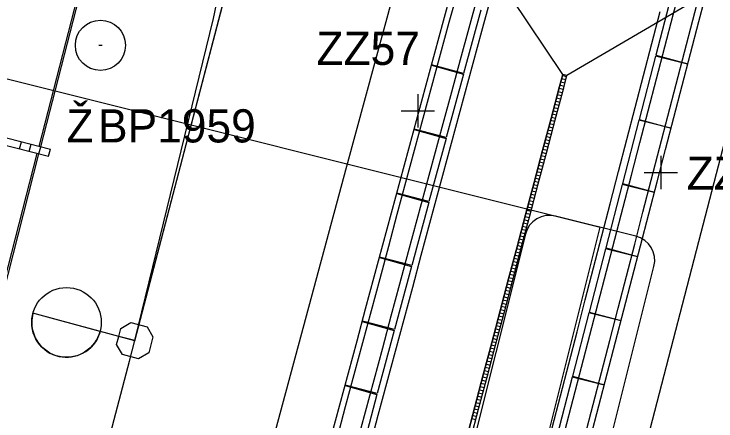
# Model space of a CAD drawing. Extents: x -733601 to -733291, y -1137892 to -1137187.
# Drawn here: x -733436.26 to -733415.08, y -1137594.6 to -1137582.33 of the extents above; entities that cross this region are included whole.
import ezdxf

# ---------------------------------------------------------------- set-up
doc = ezdxf.new("R2010")
doc.units = 0
for name, color, linetype in [('BP_ZBP_a_ZZ', 7, 'Continuous'), ('Default', 7, 'Continuous'), ('SIT_PROJ', 7, 'Continuous'), ('SIT_PUV_ZELEZNICE', 7, 'Continuous')]:
    doc.layers.add(name, color=color, linetype=linetype)

# ---------------------------------------------------------------- blocks, each defined once
blk = doc.blocks.new('T_PS_1_4')
at = {"layer": 'Default'}
blk.add_line((-12.486, 3.717), (12.486, 3.717), dxfattribs=at)
for points in [[(10.986, 8), (-10.986, 8)], [(-12.486, 6.5), (-12.486, 1.5)], [(12.486, 1.5), (12.486, 6.5)], [(-10.986, 0), (10.986, 0)]]:
    blk.add_lwpolyline(points, dxfattribs=at)
for centre, start, end in [((-10.986, 6.5), 90, 180), ((10.986, 6.5), 0, 90), ((-10.986, 1.5), 180, 270), ((10.986, 1.5), 270, 360)]:
    blk.add_arc(centre, 1.5, start, end, dxfattribs=at)
blk.add_text('SO', height=2.7, dxfattribs=at).set_placement((-11.75, 4.466))

msp = doc.modelspace()

# ---------------------------------------------------------------- linework, layer by layer
at = {"layer": 'BP_ZBP_a_ZZ'}
for p, q in [((-733433.7, -1137583.274), (-733433.6, -1137583.274)), ((-733424.074, -1137584.748), (-733424.074, -1137585.748)), ((-733424.574, -1137585.248), (-733423.574, -1137585.248)), ((-733416.743, -1137586.608), (-733416.743, -1137587.608)), ((-733417.243, -1137587.108), (-733416.243, -1137587.108))]:
    msp.add_line(p, q, dxfattribs=at)
msp.add_circle((-733433.65, -1137583.274), 0.756, dxfattribs=at)
at = {"layer": 'SIT_PROJ'}
msp.add_lwpolyline([(-733437.916, -1137583.919), (-733418.568, -1137588.759), (-733418.568, -1137588.759)], dxfattribs=at)
at = {"layer": 'SIT_PUV_ZELEZNICE'}
for p, q in [((-733435.499, -1137586.32), (-733431.375, -1137570.31)), ((-733435.451, -1137586.332), (-733431.338, -1137570.368)), ((-733419.7, -1137584.149), (-733422.437, -1137580.057)), ((-733416.398, -1137581.663), (-733416.895, -1137583.569)), ((-733415.601, -1137581.855), (-733419.575, -1137584.182)), ((-733422.176, -1137582.218), (-733422.692, -1137584.119)), ((-733416.895, -1137583.569), (-733415.93, -1137583.831)), ((-733416.903, -1137583.599), (-733417.399, -1137585.505)), ((-733415.933, -1137583.841), (-733416.903, -1137583.599)), ((-733423.662, -1137583.876), (-733422.7, -1137584.148)), ((-733422.692, -1137584.119), (-733423.66, -1137583.867)), ((-733422.7, -1137584.148), (-733423.215, -1137586.049)), ((-733419.585, -1137584.222), (-733419.711, -1137584.188)), ((-733419.575, -1137584.182), (-733419.7, -1137584.149)), ((-733419.637, -1137584.415), (-733419.762, -1137584.382)), ((-733419.611, -1137584.318), (-733419.737, -1137584.285)), ((-733419.688, -1137584.608), (-733419.814, -1137584.575)), ((-733419.662, -1137584.512), (-733419.788, -1137584.478)), ((-733419.765, -1137584.898), (-733419.891, -1137584.865)), ((-733419.739, -1137584.801), (-733419.865, -1137584.768)), ((-733419.714, -1137584.705), (-733419.839, -1137584.672)), ((-733419.816, -1137585.091), (-733419.942, -1137585.058)), ((-733419.79, -1137584.995), (-733419.916, -1137584.962)), ((-733419.867, -1137585.285), (-733419.993, -1137585.252)), ((-733419.842, -1137585.188), (-733419.967, -1137585.155)), ((-733419.919, -1137585.478), (-733420.044, -1137585.445)), ((-733419.893, -1137585.381), (-733420.019, -1137585.348)), ((-733419.97, -1137585.671), (-733420.096, -1137585.638)), ((-733419.944, -1137585.575), (-733420.07, -1137585.541)), ((-733417.407, -1137585.534), (-733417.903, -1137587.441)), ((-733416.437, -1137585.776), (-733417.407, -1137585.534)), ((-733417.399, -1137585.505), (-733416.434, -1137585.767)), ((-733437.194, -1137585.883), (-733435.16, -1137586.407)), ((-733424.186, -1137585.807), (-733423.223, -1137586.078)), ((-733423.215, -1137586.049), (-733424.183, -1137585.797)), ((-733420.021, -1137585.865), (-733420.147, -1137585.831)), ((-733419.996, -1137585.768), (-733420.121, -1137585.735)), ((-733437.249, -1137586.096), (-733435.215, -1137586.62)), ((-733423.223, -1137586.078), (-733423.738, -1137587.979)), ((-733420.098, -1137586.155), (-733420.224, -1137586.121)), ((-733420.073, -1137586.058), (-733420.198, -1137586.025)), ((-733420.047, -1137585.961), (-733420.173, -1137585.928)), ((-733436.087, -1137586.396), (-733436.032, -1137586.183)), ((-733435.796, -1137586.471), (-733435.741, -1137586.258)), ((-733435.506, -1137586.546), (-733435.451, -1137586.332)), ((-733420.15, -1137586.348), (-733420.275, -1137586.315)), ((-733420.124, -1137586.251), (-733420.25, -1137586.218)), ((-733438.815, -1137599.192), (-733435.554, -1137586.533)), ((-733438.766, -1137599.204), (-733435.506, -1137586.546)), ((-733435.215, -1137586.62), (-733435.16, -1137586.407)), ((-733420.201, -1137586.541), (-733420.327, -1137586.508)), ((-733420.175, -1137586.445), (-733420.301, -1137586.411)), ((-733420.252, -1137586.735), (-733420.378, -1137586.701)), ((-733420.226, -1137586.638), (-733420.352, -1137586.605)), ((-733420.303, -1137586.928), (-733420.429, -1137586.895)), ((-733420.278, -1137586.831), (-733420.403, -1137586.798)), ((-733420.38, -1137587.218), (-733420.506, -1137587.185)), ((-733420.355, -1137587.121), (-733420.48, -1137587.088)), ((-733420.329, -1137587.025), (-733420.455, -1137586.991)), ((-733420.431, -1137587.411), (-733420.557, -1137587.378)), ((-733420.406, -1137587.315), (-733420.532, -1137587.281)), ((-733420.483, -1137587.605), (-733420.608, -1137587.571)), ((-733420.457, -1137587.508), (-733420.583, -1137587.475)), ((-733417.91, -1137587.47), (-733418.406, -1137589.377)), ((-733416.94, -1137587.712), (-733417.91, -1137587.47)), ((-733417.903, -1137587.441), (-733416.938, -1137587.702)), ((-733424.708, -1137587.737), (-733423.745, -1137588.008)), ((-733423.738, -1137587.979), (-733424.705, -1137587.728)), ((-733420.534, -1137587.798), (-733420.66, -1137587.765)), ((-733420.508, -1137587.701), (-733420.634, -1137587.668)), ((-733423.745, -1137588.008), (-733424.259, -1137589.91)), ((-733420.585, -1137587.991), (-733420.711, -1137587.958)), ((-733420.559, -1137587.895), (-733420.685, -1137587.861)), ((-733420.662, -1137588.281), (-733420.788, -1137588.248)), ((-733420.636, -1137588.185), (-733420.762, -1137588.151)), ((-733420.611, -1137588.088), (-733420.736, -1137588.055)), ((-733420.713, -1137588.475), (-733420.839, -1137588.441)), ((-733420.688, -1137588.378), (-733420.813, -1137588.345)), ((-733420.764, -1137588.668), (-733420.89, -1137588.635)), ((-733420.739, -1137588.571), (-733420.864, -1137588.538)), ((-733420.816, -1137588.861), (-733420.941, -1137588.828)), ((-733420.79, -1137588.765), (-733420.916, -1137588.731)), ((-733420.867, -1137589.055), (-733420.992, -1137589.021)), ((-733420.841, -1137588.958), (-733420.967, -1137588.925)), ((-733420.943, -1137589.345), (-733421.069, -1137589.311)), ((-733420.918, -1137589.248), (-733421.044, -1137589.215)), ((-733420.892, -1137589.151), (-733421.018, -1137589.118)), ((-733420.995, -1137589.538), (-733421.12, -1137589.505)), ((-733420.969, -1137589.441), (-733421.095, -1137589.408)), ((-733418.414, -1137589.406), (-733418.909, -1137591.313)), ((-733417.443, -1137589.648), (-733418.414, -1137589.406)), ((-733418.406, -1137589.377), (-733417.441, -1137589.638)), ((-733425.229, -1137589.668), (-733424.267, -1137589.938)), ((-733424.259, -1137589.91), (-733425.227, -1137589.659)), ((-733421.046, -1137589.731), (-733421.171, -1137589.698)), ((-733421.02, -1137589.635), (-733421.146, -1137589.601)), ((-733424.267, -1137589.938), (-733424.779, -1137591.84)), ((-733421.097, -1137589.925), (-733421.223, -1137589.891)), ((-733421.071, -1137589.828), (-733421.197, -1137589.795)), ((-733421.148, -1137590.118), (-733421.274, -1137590.085)), ((-733421.123, -1137590.021), (-733421.248, -1137589.988)), ((-733421.199, -1137590.311), (-733421.325, -1137590.278)), ((-733421.174, -1137590.215), (-733421.299, -1137590.181)), ((-733421.276, -1137590.601), (-733421.402, -1137590.568)), ((-733421.25, -1137590.505), (-733421.376, -1137590.471)), ((-733421.225, -1137590.408), (-733421.35, -1137590.375)), ((-733421.327, -1137590.795), (-733421.453, -1137590.761)), ((-733421.301, -1137590.698), (-733421.427, -1137590.665)), ((-733421.378, -1137590.988), (-733421.504, -1137590.955)), ((-733421.353, -1137590.891), (-733421.478, -1137590.858)), ((-733421.429, -1137591.181), (-733421.555, -1137591.148)), ((-733421.404, -1137591.085), (-733421.529, -1137591.052)), ((-733432.613, -1137592.178), (-733435.685, -1137591.349)), ((-733421.48, -1137591.375), (-733421.606, -1137591.342)), ((-733421.455, -1137591.278), (-733421.581, -1137591.245)), ((-733418.917, -1137591.342), (-733419.411, -1137593.249)), ((-733417.946, -1137591.583), (-733418.917, -1137591.342)), ((-733418.909, -1137591.313), (-733417.944, -1137591.574)), ((-733433.033, -1137591.809), (-733432.728, -1137591.63)), ((-733432.728, -1137591.63), (-733432.244, -1137591.757)), ((-733425.75, -1137591.599), (-733424.787, -1137591.869)), ((-733424.779, -1137591.84), (-733425.747, -1137591.59)), ((-733421.557, -1137591.665), (-733421.683, -1137591.632)), ((-733421.531, -1137591.568), (-733421.657, -1137591.535)), ((-733421.506, -1137591.471), (-733421.632, -1137591.438)), ((-733433.096, -1137592.051), (-733433.033, -1137591.809)), ((-733432.244, -1137591.757), (-733432.066, -1137592.062)), ((-733421.608, -1137591.858), (-733421.734, -1137591.825)), ((-733421.583, -1137591.762), (-733421.708, -1137591.728)), ((-733433.16, -1137592.292), (-733433.096, -1137592.051)), ((-733432.613, -1137592.177), (-733433.096, -1137592.051)), ((-733432.066, -1137592.062), (-733432.192, -1137592.546)), ((-733424.787, -1137591.869), (-733425.299, -1137593.771)), ((-733421.659, -1137592.052), (-733421.785, -1137592.018)), ((-733421.634, -1137591.955), (-733421.759, -1137591.922)), ((-733421.71, -1137592.245), (-733421.836, -1137592.212)), ((-733421.685, -1137592.148), (-733421.81, -1137592.115)), ((-733432.981, -1137592.598), (-733433.16, -1137592.292)), ((-733421.761, -1137592.438), (-733421.887, -1137592.405)), ((-733421.736, -1137592.342), (-733421.861, -1137592.308)), ((-733432.497, -1137592.724), (-733432.981, -1137592.598)), ((-733432.192, -1137592.546), (-733432.497, -1137592.724)), ((-733421.838, -1137592.728), (-733421.964, -1137592.695)), ((-733421.812, -1137592.632), (-733421.938, -1137592.598)), ((-733421.787, -1137592.535), (-733421.913, -1137592.502)), ((-733421.889, -1137592.922), (-733422.015, -1137592.888)), ((-733421.863, -1137592.825), (-733421.989, -1137592.792)), ((-733421.94, -1137593.115), (-733422.066, -1137593.082)), ((-733421.915, -1137593.018), (-733422.04, -1137592.985)), ((-733421.991, -1137593.308), (-733422.117, -1137593.275)), ((-733421.966, -1137593.212), (-733422.091, -1137593.179)), ((-733419.419, -1137593.278), (-733419.914, -1137595.185)), ((-733418.449, -1137593.519), (-733419.419, -1137593.278)), ((-733419.411, -1137593.249), (-733418.446, -1137593.51)), ((-733426.269, -1137593.531), (-733425.306, -1137593.8)), ((-733425.299, -1137593.771), (-733426.267, -1137593.521)), ((-733422.042, -1137593.502), (-733422.168, -1137593.469)), ((-733422.017, -1137593.405), (-733422.142, -1137593.372)), ((-733422.119, -1137593.792), (-733422.244, -1137593.759)), ((-733422.093, -1137593.695), (-733422.219, -1137593.662)), ((-733422.068, -1137593.599), (-733422.193, -1137593.565)), ((-733425.306, -1137593.8), (-733425.817, -1137595.702)), ((-733422.17, -1137593.985), (-733422.295, -1137593.952)), ((-733422.144, -1137593.889), (-733422.27, -1137593.855)), ((-733422.221, -1137594.179), (-733422.346, -1137594.145)), ((-733422.195, -1137594.082), (-733422.321, -1137594.049)), ((-733422.272, -1137594.372), (-733422.397, -1137594.339)), ((-733422.246, -1137594.275), (-733422.372, -1137594.242)), ((-733422.323, -1137594.565), (-733422.448, -1137594.532)), ((-733422.297, -1137594.469), (-733422.423, -1137594.436))]:
    msp.add_line(p, q, dxfattribs=at)
for points in [[(-733432.613, -1137592.177), (-733430.241, -1137582.464), (-733428.195, -1137572.675), (-733426.476, -1137562.825), (-733425.101, -1137553.045), (-733425.086, -1137552.922), (-733424.525, -1137548.394), (-733423.804, -1137543.005), (-733422.199, -1137533.135), (-733420.237, -1137523.33), (-733417.92, -1137513.602), (-733417.278, -1137511.157), (-733415.349, -1137503.939), (-733412.766, -1137494.278), (-733410.183, -1137484.617), (-733407.6, -1137474.957), (-733405.017, -1137465.296), (-733402.434, -1137455.636), (-733401.342, -1137451.549), (-733399.798, -1137445.99), (-733397.493, -1137438.369), (-733396.877, -1137436.426), (-733393.987, -1137427.309)], [(-733432.613, -1137592.178), (-733428.404, -1137576.104), (-733424.195, -1137560.031)], [(-733432.612, -1137592.177), (-733430.242, -1137583.123), (-733427.708, -1137573.449), (-733425.176, -1137563.776), (-733424.321, -1137560.514)], [(-733459.36, -1137757.582), (-733458.338, -1137753.729), (-733455.783, -1137744.061), (-733453.237, -1137734.391), (-733450.698, -1137724.719), (-733448.167, -1137715.044), (-733445.645, -1137705.368), (-733443.13, -1137695.689), (-733440.624, -1137686.008), (-733440.158, -1137684.204), (-733438.123, -1137676.326), (-733435.622, -1137666.644), (-733433.121, -1137656.962), (-733430.62, -1137647.279), (-733428.119, -1137637.597), (-733425.618, -1137627.915), (-733423.422, -1137619.411), (-733423.117, -1137618.233), (-733420.616, -1137608.551), (-733418.11, -1137598.87), (-733415.599, -1137589.19), (-733413.078, -1137579.513), (-733412.782, -1137578.384)], [(-733426.685, -1137595.077), (-733426.425, -1137594.112), (-733426.166, -1137593.146), (-733425.907, -1137592.181), (-733425.647, -1137591.216), (-733425.387, -1137590.251), (-733425.126, -1137589.286), (-733424.866, -1137588.321), (-733424.605, -1137587.356), (-733424.344, -1137586.391), (-733424.083, -1137585.426), (-733423.821, -1137584.461), (-733423.559, -1137583.496), (-733423.297, -1137582.532), (-733423.035, -1137581.567)], [(-733426.511, -1137595.124), (-733426.252, -1137594.158), (-733425.992, -1137593.193), (-733425.733, -1137592.228), (-733425.473, -1137591.263), (-733425.213, -1137590.298), (-733424.953, -1137589.333), (-733424.692, -1137588.368), (-733424.431, -1137587.403), (-733424.17, -1137586.438), (-733423.909, -1137585.473), (-733423.647, -1137584.508), (-733423.386, -1137583.544), (-733423.124, -1137582.579), (-733422.861, -1137581.615)], [(-733469.582, -1137755.14), (-733468.663, -1137751.534), (-733466.195, -1137741.843), (-733463.726, -1137732.153), (-733461.257, -1137722.462), (-733458.789, -1137712.772), (-733456.32, -1137703.081), (-733453.852, -1137693.391), (-733451.383, -1137683.701), (-733451.044, -1137682.371), (-733448.914, -1137674.01), (-733446.443, -1137664.32), (-733443.966, -1137654.632), (-733441.48, -1137644.946), (-733438.982, -1137635.263), (-733436.47, -1137625.584), (-733433.94, -1137615.909), (-733431.39, -1137606.239), (-733431.038, -1137604.913), (-733428.815, -1137596.577), (-733426.217, -1137586.92), (-733424.808, -1137581.736)], [(-733425.912, -1137595.284), (-733425.653, -1137594.319), (-733425.394, -1137593.354), (-733425.134, -1137592.389), (-733424.874, -1137591.424), (-733424.614, -1137590.459), (-733424.354, -1137589.494), (-733424.093, -1137588.529), (-733423.833, -1137587.564), (-733423.572, -1137586.6), (-733423.31, -1137585.635), (-733423.049, -1137584.671), (-733422.787, -1137583.706), (-733422.525, -1137582.742), (-733422.263, -1137581.777)], [(-733425.526, -1137595.388), (-733425.267, -1137594.423), (-733425.007, -1137593.458), (-733424.748, -1137592.493), (-733424.488, -1137591.528), (-733424.228, -1137590.563), (-733423.968, -1137589.598), (-733423.707, -1137588.634), (-733423.447, -1137587.669), (-733423.186, -1137586.704), (-733422.924, -1137585.74), (-733422.663, -1137584.775), (-733422.401, -1137583.811), (-733422.139, -1137582.847), (-733421.877, -1137581.882)], [(-733419.636, -1137594.909), (-733419.385, -1137593.943), (-733419.134, -1137592.977), (-733418.884, -1137592.012), (-733418.633, -1137591.046), (-733418.382, -1137590.08), (-733418.131, -1137589.114), (-733417.88, -1137588.149), (-733417.629, -1137587.183), (-733417.378, -1137586.217), (-733417.127, -1137585.251), (-733416.875, -1137584.286), (-733416.624, -1137583.32), (-733416.372, -1137582.355), (-733416.201, -1137581.697)], [(-733419.035, -1137595.065), (-733418.785, -1137594.099), (-733418.534, -1137593.133), (-733418.284, -1137592.167), (-733418.033, -1137591.202), (-733417.782, -1137590.236), (-733417.531, -1137589.27), (-733417.28, -1137588.305), (-733417.029, -1137587.339), (-733416.778, -1137586.373), (-733416.527, -1137585.408), (-733416.275, -1137584.442), (-733416.024, -1137583.476), (-733415.772, -1137582.511), (-733415.601, -1137581.855)], [(-733418.861, -1137595.11), (-733418.611, -1137594.144), (-733418.36, -1137593.178), (-733418.109, -1137592.213), (-733417.859, -1137591.247), (-733417.608, -1137590.281), (-733417.357, -1137589.316), (-733417.106, -1137588.35), (-733416.855, -1137587.384), (-733416.604, -1137586.419), (-733416.352, -1137585.453), (-733416.101, -1137584.487), (-733415.85, -1137583.522), (-733415.598, -1137582.556), (-733415.427, -1137581.901)], [(-733420.023, -1137594.809), (-733419.772, -1137593.843), (-733419.522, -1137592.877), (-733419.271, -1137591.911), (-733419.02, -1137590.945), (-733418.769, -1137589.98), (-733418.518, -1137589.014), (-733418.267, -1137588.048), (-733418.016, -1137587.082), (-733417.765, -1137586.116), (-733417.514, -1137585.151), (-733417.262, -1137584.185), (-733417.011, -1137583.219), (-733416.759, -1137582.254)], [(-733422.482, -1137595.17), (-733422.228, -1137594.205), (-733421.973, -1137593.239), (-733421.718, -1137592.274), (-733421.463, -1137591.308), (-733421.208, -1137590.343), (-733420.952, -1137589.378), (-733420.697, -1137588.412), (-733420.441, -1137587.447), (-733420.185, -1137586.482), (-733419.929, -1137585.516), (-733419.673, -1137584.551), (-733419.616, -1137584.336), (-733419.575, -1137584.182), (-733419.7, -1137584.149), (-733419.798, -1137584.518), (-733420.055, -1137585.483), (-733420.311, -1137586.448), (-733420.567, -1137587.414), (-733420.822, -1137588.379), (-733421.078, -1137589.344), (-733421.333, -1137590.31), (-733421.589, -1137591.275), (-733421.844, -1137592.241), (-733422.099, -1137593.206), (-733422.353, -1137594.172), (-733422.608, -1137595.137)], [(-733422.608, -1137595.137), (-733422.353, -1137594.172), (-733422.099, -1137593.206), (-733421.844, -1137592.241), (-733421.589, -1137591.275), (-733421.333, -1137590.31), (-733421.078, -1137589.344), (-733420.822, -1137588.379), (-733420.567, -1137587.414), (-733420.311, -1137586.448), (-733420.055, -1137585.483), (-733419.798, -1137584.518), (-733419.7, -1137584.149)], [(-733422.482, -1137595.17), (-733422.228, -1137594.205), (-733421.973, -1137593.239), (-733421.718, -1137592.274), (-733421.463, -1137591.308), (-733421.208, -1137590.343), (-733420.952, -1137589.378), (-733420.697, -1137588.412), (-733420.441, -1137587.447), (-733420.185, -1137586.482), (-733419.929, -1137585.516), (-733419.673, -1137584.551), (-733419.575, -1137584.182)], [(-733433.657, -1137591.896), (-733435.685, -1137591.349)], [(-733473.591, -1137751.638), (-733472.603, -1137747.76), (-733470.135, -1137738.069), (-733467.666, -1137728.379), (-733465.198, -1137718.688), (-733462.729, -1137708.998), (-733460.26, -1137699.307), (-733457.792, -1137689.617), (-733455.323, -1137679.926), (-733452.855, -1137670.236), (-733450.386, -1137660.545), (-733448.734, -1137654.061), (-733447.917, -1137650.855), (-733445.432, -1137641.168), (-733442.928, -1137631.487), (-733440.405, -1137621.811), (-733437.862, -1137612.139), (-733437.8, -1137611.906), (-733435.314, -1137602.469), (-733432.775, -1137592.797), (-733432.613, -1137592.177)]]:
    msp.add_lwpolyline(points, dxfattribs=at)
msp.add_circle((-733434.672, -1137591.627), 1.05, dxfattribs=at)
for start, end in [(164.6729, 180), (180, 345.133)]:
    msp.add_arc((-733434.672, -1137591.627), 1.05, start, end, dxfattribs=at)

# ---------------------------------------------------------------- block references
at = {"layer": 'SIT_PROJ', "xscale": 0.4999999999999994, "yscale": 0.49999999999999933, "rotation": 75.93557209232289}
msp.add_blockref('T_PS_1_4', (-733418.283, -1137595.267), dxfattribs=at)

# ---------------------------------------------------------------- texts
at = {"layer": 'BP_ZBP_a_ZZ'}
for s, p in [('ZZ57', (-733427.132, -1137583.864)), ('Ž', (-733434.674, -1137586.202)), ('BP1959', (-733433.722, -1137586.202)), ('ZZ58', (-733415.962, -1137587.626))]:
    msp.add_text(s, height=1, dxfattribs=at).set_placement(p)

doc.saveas('drawing.dxf')
